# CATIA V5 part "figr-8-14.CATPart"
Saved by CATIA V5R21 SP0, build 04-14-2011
Part number: Part1
Bounding box of the stored display mesh (mm): x 4.549 to 89.781, y -52.238 to 26.36, z 54 to 147.773
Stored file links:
  D:\CATIA V5R21 E-RESOURCES\CATIA-V5R21\catia-v5r21-prt\c08-catia-v5r20-prt\c08-catia-v5r21-figr-8-14.CATPart
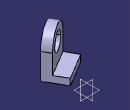
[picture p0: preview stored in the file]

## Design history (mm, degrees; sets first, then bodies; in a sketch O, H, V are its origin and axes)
Body1 (main body)
  Sketch1 on yz-plane, origin (0, 0, 0), H (0, 1, 0), V (0, 0, 1)
    point P1 (-104.4861, 0)
    line L1 (-104.4861, 0) -> (-104.4861, 44.267)
    arc A1 centre (-69.7903, 44.267) radius 34.6958 from (-104.4861, 44.267) to (-35.0946, 44.267) cw
    line L2 (-35.0946, 44.267) -> (-35.0946, 0)
    point P5 (-35.0946, 0)
    line L3 (-35.0946, 0) -> (-104.4861, 0)
    circle A2 centre (-69.7903, 44.267) radius 19.5413
    coincidence: P1 H, P5 H
    vertical: L1 V
    tangency: A1 L1, L2 A1
    horizontal: L3 H
  Pad1: profile Sketch1, direction (1, 0, 0), length 20
  Sketch2 on face of Pad1, origin (0, 0, 0), H (0, -1, 0), V (0, 0, 1)
    point P1 (35.0946, 0)
    line L1 (35.0946, 0) -> (104.4861, 0)
    line L2 (104.4861, 0) -> (104.4861, -15)
    line L3 (104.4861, -15) -> (35.0946, -15)
    line L4 (35.0946, -15) -> (35.0946, 0)
    reference projected line E1 (35.0946, 0) -> (35.0946, 44.267) from edge [face of Pad1 | face of Pad1]
    reference projected line E2 (104.4861, 44.267) -> (104.4861, 0) from edge [face of Pad1 | face of Pad1]
    distance L3 L1 = 15
    coincidence: P1 H, L4 E1, L2 E2
    horizontal: L1 H, L3 H
    vertical: L2 V, L4 V
  Pad2: profile Sketch2, direction (1, 0, 0), length 50
  Translate1: ToTransfor Pad2, Direction xy-plane, Length 69
  Rotate1: ToTransfor Translate1, Axis edge, Angle 121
